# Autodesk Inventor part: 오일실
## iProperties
IsCustomPart: 1
Company: 한국ATC센터
Created: 2014-10
Part Number: 오일실
Material: 고무
Description: 오일-실
Document SubType Name: Modeling
Standard: KS B 2804
Designer: 한국ATC센터
Standards Organization: KS
Language: ko-KR
Size Designation: S - 25 40 8
Categories: <MemberInstance><Categories><Category DisplayName="샤프트 부품" InternalName="7f7aeb1f-a693-4053-b835-cee3144e0d98" Mnemonic="SHFT"><Category DisplayName="실링" Intern
Density: 0.93 g/cm^3
Mass: 2.48215 g
Surface Area: 40.3381 cm^2
Volume: 2.66898 cm^3
Author: KYOUNG IL JANG
Revision Number: 1
